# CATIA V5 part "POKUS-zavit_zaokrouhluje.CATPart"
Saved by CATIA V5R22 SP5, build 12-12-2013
Part number: 4980013710
Definition: 4980013710
Nomenclature: 4980013710
Property "GPDM_CREATED_BY": "Peter Cermak"
Property "GPDM_CREATED_ON": "2016-04-12"
Property "GPDM_VERSION": 1
Property "GPDM_MODIFIED_ON": "2016-04-12"
Property "GPDM_MODIFIED_BY": "Peter Cermak"
Property "MATERIAL": "Start_Material"
Property "SURFACE_AREA": 200817
Property "GMASS": "39,707"
Property "DESIGN_NUMBER": "4980013710"
Property "DESIGN_NAME_1": "Engine Housing"
Property "MATURITY": "1"
Property "PLANT": "Please select a location"
Property "DEPARTMENT": "Please select a department"
Property "C3PNG_ItemName": "Engine Housing"
Material "Start_Material": density 100000 kg/m3
Bounding box of the stored display mesh (mm): x 0 to 229.3, y -69 to 197, z -129.7 to 184.7
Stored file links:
  C:\Users\jmaur\Desktop\POKUS-zavit_zaokrouhluje.CATPart
  C:\PWB_XMAP\CATIA_GFT\Material\GFT-CAD-Materials.CATMaterial
  CATMaterial1.CATMaterial
  L:\Antriebe\Projekte\2016\M-16-0005_GET_Gehaeusekonstruktion_8DCL900\8_CAD-Data\int\2016_05_09_FERR_Engine_Housing\4980013710\4980013790.CATPart
  C:\Users\zmuchna\Desktop\Ferrari\motoranschlussgehaeuse\498_housing_fer_cp_cp.CATPart
  L:\Antriebe\Projekte\2016\M-16-0005_GET_Gehaeusekonstruktion_8DCL900\8_CAD-Data\int\2016_05_09_FERR_Engine_Housing\4980013710\4980013710_cp.CATPart
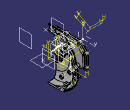
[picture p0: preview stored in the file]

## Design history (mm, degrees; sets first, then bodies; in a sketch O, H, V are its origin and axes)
Parameters
  SURFACE_AREA = 0.200817 (area) {= round(smartWetarea(Body1),"mm2",0)}
  pro_mp_mass = 39.7072 (mass)
  pro_mp_alt_mass = 5 (mass)
  GMASS = 39.7072 (mass)
  pro_mp_source = "Geometry"
AxisSystem1 "M-A-S-T-E-R": origin (0, 0, 0), X (1, 0, 0), Y (0, 1, 0), Z (0, 0, 1)
Set1 "Geometrical Set"
  Line1 "Center_Line": type PtPt, FirstPoint {point type Coord, X -50, Y 0, Z 0}, SecondPoint {point type Coord, X 50, Y 0, Z 0}
  Point1 "Center_Point": (0, 0, 0)
Set2 "Machining_Support"
  Plane1: type Offset, RefPlane Plane6, Offset 1.6
  Plane2 "PL_center_level_1": type Offset, RefPlane Plane5, Offset 12.78, reversed
  Plane3 "PL_center_level_2": type Offset, RefPlane Plane5, Offset 14.78, reversed
Set3
  Plane4 "PL_Flange_Engine_Housing_Front": stored without definition
  Plane5 "PL_Flange_Engine_Housing_Rear": stored without definition
  Plane6 "PL_Oil_Nossel": stored without definition
  Plane7 "PL_Bolts_Contact_Surface_Engine_Side": stored without definition
  Plane8 "PL_Bolts_Contact_Surface_Engine_Side_Lower": stored without definition
  Plane9 "PL_Oil_Nossel_1": stored without definition
  Plane10 "PL_Oil-Riser_2": stored without definition
  Sketch1 "S_Bolts_Differential_Housing_Front", origin (157, 0, 0), H (0, 1, 0), V (0, 0, 1)
    point P1 (65, 142)
    point P2 (150, 138.5)
    point P3 (122.5, -6)
    point P4 (92, -43)
    point P5 (187, 24)
    point P6 (186, 97)
    point P7 (41, -92)
  Sketch2 "S_Bolts_Engine_Housing_Front", origin (209.3, 0, 0), H (0, 1, 0), V (0, 0, 1)
    point P1 (162.619, 38)
    point P2 (107.261, 128)
    point P3 (29, 165)
    point P4 (84, -112.5)
    point P5 (165.5, -16)
  Sketch3 "S_Hydr_Holes", origin (0, 29.4838, 55.6851), H (-1, 0, 0), V (0, -0.8838, 0.4679), geometry linked from another document
  Sketch4 "S_Hydr_Holes_1", origin (0, 43.5217, 82.1981), H (-1, 0, 0), V (0, -0.8838, 0.4679), geometry linked from another document
  Sketch5 "P_Oil_Riser", origin (157.28, 0, 0), H (0, -1, 0), V (0, 0, 1), geometry linked from another document
  Sketch6 "PL_Oil_Riser_2", origin (0, 0, -58), H (1, 0, 0), V (0, -1, 0), geometry linked from another document
Body1 "Rear_Cover" (main body), material "Start_Material"
  Body2 "Raw_Part"
    Solid1: solid without history
  Add1: tool Body2
  Body3 "Machining"
    Body4 "Flanges"
      Body5 "Engine_Flange"
        Sketch7 on Plane4, origin (209.3, 0, 0), H (0, 1, 0), V (0, 0, 1)
          line L1 (-228.2306, 219.2479) -> (234.054, 219.2479)
          line L2 (234.054, 219.2479) -> (234.054, -157.1798)
          line L3 (234.054, -157.1798) -> (-228.2306, -157.1798)
          line L4 (-228.2306, -157.1798) -> (-228.2306, 219.2479)
          horizontal: L1 H, L3 H
          vertical: L2 V, L4 V
          fix: L1, L2, L3, L4
        Pad1: profile Sketch7, direction (1, 0, 0), length 20
      Add2: tool Body5
      Body6 "Diff_Flange"
        Sketch8 on Plane5, origin (157.28, 0, 0), H (0, 1, 0), V (0, 0, -1)
          line L1 (225.392, -220.6587) -> (-229.8439, -220.6587)
          line L2 (-229.8439, -220.6587) -> (-229.8439, 158.3338)
          line L3 (-229.8439, 158.3338) -> (225.392, 158.3338)
          line L4 (225.392, 158.3338) -> (225.392, -220.6587)
          arc A1 centre (0, 0) radius 75 from (70.3464, -26.0075) to (-5.6638, -74.7858) ccw
          intersected line E1 through (29.4838, -55.6851) direction (0.8838, 0.4679) from Plane6
          line L5 (-5.6638, -74.7858) -> (11.4424, -107.0938)
          line L6 (11.4424, -107.0938) -> (90.9813, -64.9801)
          line L7 (90.9813, -64.9801) -> (70.3464, -26.0075)
          radius A1 = 75
          distance L5 O = 40
          distance L5 L7 = 90
          distance L6 O = 100
          horizontal: L1 H, L3 H
          vertical: L2 V, L4 V
          fix: L3, L4, L1, L2
          perpendicularity: L5 E1
          parallelism: L6 E1
        Pad2: profile Sketch8, direction (-1, 0, 0), length 20
      Add3: tool Body6
    Add4: tool Body4
    Body7 "Diff_Flange_Bolts"
      Sketch9 on Plane5, origin (157.28, -70, 142), H (0, 1, 0), V (0, 0, 1)
        point P1 (135, 0)
        reference projected point E1 (135, 0) from Sketch1.P1
        coincidence: P1 E1
      Hole1: placed by Sketch9, at (157.28, 65, 142) direction (1, 0, 0), diameter 9, depth 25, V-bottom angle 130
      UserPattern1: of the body so far, copies 7, at the points of Sketch1
    Add5: tool Body7
    Body8 "Engine_Flange_Bolts"
      Sketch10 on Plane4, origin (209.3, -52, 165), H (0, 1, 0), V (0, 0, 1)
        point P1 (81, 0)
        reference projected point E1 (81, 0) from Sketch2.P3
        coincidence: P1 E1
      Hole2: placed by Sketch10, at (209.3, 29, 165) direction (-1, 0, 0), diameter 9, depth 25, V-bottom angle 130
      UserPattern2: of the body so far, copies 5, at the points of Sketch2
    Add6: tool Body8
    Body9 "Center_machining"
      Sketch11 on ZX plane of AxisSystem1, origin (0, 0, 0), H (1, 0, 0), V (0, 0, 1)
        line L1 (132.1, 32.8) -> (137.5, 32.8)
        line L2 (137.5, 32.8) -> (137.5, 37.8)
        line L3 (137.5, 37.8) -> (142.5, 37.8)
        line L4 (142.5, 37.8) -> (142.5, 32.8)
        point P4 (142.5, 32.8)
        line L5 (142.5, 32.8) -> (148.5, 32.8)
        line L6 (148.5, 32.8) -> (148.5, 39.3)
        line L7 (148.5, 39.3) -> (157.5, 39.3)
        line L8 (157.5, 39.3) -> (157.5, 32.8)
        line L9 (157.5, 32.8) -> (162, 32.8)
        line L10 (162, 32.8) -> (162, 31.25)
        line L11 (162, 31.25) -> (163.5, 31.25)
        line L12 (163.5, 31.25) -> (163.5, 31)
        line L13 (163.5, 31) -> (171.3, 31)
        line L14 (171.3, 31) -> (171.3, 27)
        line L15 (171.3, 27) -> (183.5, 27)
        line L16 (183.5, 27) -> (183.5, 30)
        line L17 (183.5, 30) -> (190, 30)
        line L18 (190, 30) -> (190, 0)
        line L19 (132.1, 32.8) -> (132.1, 40)
        line L20 (132.1, 40) -> (125, 40)
        line L21 (125, 40) -> (125, 0)
        point P19 (125, 0)
        point P20 (190, 0)
        construction line L22 (183.5, 23.9368) -> (182.4657, 23.5603)
        construction arc A1 centre (182.1233, 24.5021) radius 1.0021 from (182.1237, 23.5) to (182.4657, 23.5603) ccw
        construction arc A2 centre (173.4767, 24.5021) radius 1.0021 from (173.1343, 23.5603) to (173.4763, 23.5) ccw
        construction line L23 (173.1343, 23.5603) -> (171.8, 24.046)
        construction arc A3 centre (170.9999, 30.6999) radius 0.3001 from (171.3, 30.7) to (171, 31) ccw
        construction arc A4 centre (161.4998, 32.2998) radius 0.5002 from (162, 32.3) to (161.5, 32.8) ccw
        construction arc A5 centre (156.9998, 38.7998) radius 0.5002 from (157.5, 38.8) to (157, 39.3) ccw
        construction arc A6 centre (149.0002, 38.7998) radius 0.5002 from (149, 39.3) to (148.5, 38.8) ccw
        construction line L24 (133.0856, 32.8) -> (131.7, 33.6)
        distance L9 H = 32.8
        distance L16 V = 183.5
        distance L18 V = 190
        distance L17 H = 30
        distance L1 H = 32.8
        distance L19 V = 132.1
        distance L20 H = 40
        distance L21 V = 125
        distance L7 H = 39.3
        distance L8 V = 157.5
        distance L6 V = 148.5
        distance L4 V = 142.5
        distance L12 V = 163.5
        distance L10 V = 162
        distance L11 H = 31.25
        distance L15 H = 27
        distance L14 V = 171.3
        distance L2 V = 137.5
        distance L3 H = 37.8
        distance L13 H = 31
        horizontal: L1 H, L3 H, L5 H, L7 H, L9 H, L11 H, L13 H, L15 H, L17 H, L20 H
        vertical: L2 V, L4 V, L6 V, L8 V, L10 V, L12 V, L14 V, L16 V, L18 V, L19 V, L21 V
        coincidence: P4 L1, P19 H, P20 H
      Shaft1: profile Sketch11, axis Sketch11.H, angle 360
      Fillet1: radius 0.5, on edge [face of Shaft1 from Sketch11.L7 | face of Shaft1 from Sketch11.L8]; edge [face of Shaft1 from Sketch11.L6 | face of Shaft1 from Sketch11.L7]; edge [face of Shaft1 from Sketch11.L9 | face of Shaft1 from Sketch11.L10]; edge [face of Shaft1 from Sketch11.L3 | face of Shaft1 from Sketch11.L4]
      Fillet2: radius 2.5, on edge [face of Shaft1 from Sketch11.L2 | face of Shaft1 from Sketch11.L3]
      Fillet3: radius 0.2, on edge [face of Shaft1 from Sketch11.L13 | face of Shaft1 from Sketch11.L14]
      Chamfer1: length 1.4, angle 30, on edge [face of Shaft1 from Sketch11.L19 | face of Shaft1 from Sketch11.L1]
      Chamfer2: length 0.5, angle 45, on edge [face of Shaft1 from Sketch11.L14 | face of Shaft1 from Sketch11.L15]
    Add7: tool Body9
    Body10 "Mounting_Contact_Surfaces_Engine_Side"
      Body11 "Mounting_Contact_Surfaces_Engine_Side_Higher"
        Sketch12 on Plane7, origin (187.4, 29, 165), H (0, 1, 0), V (0, 0, -1)
          circle A1 centre (0, 0) radius 12.5
          radius A1 = 12.5
        Pad3: profile Sketch12, direction (-1, 0, 0), length 15
        UserPattern3: of the body so far, copies 5, at the points of Sketch2
      Add8: tool Body11
      Body12 "Mounting_Contact_Surfaces_Engine_Side_Lower"
        Sketch13 on end face of Pad1, origin (229.3, 162.619, 38), H (0, 1, 0), V (0, 0, -1)
          circle A1 centre (0, 0) radius 12.5
          point P1 (0, 0)
          radius A1 = 12.5
          coincidence: P1 O
        Pad4: profile Sketch13, direction (-1, 0, 0), length 15
        UserPattern4: of the body so far, copies 5, at the points of Sketch2
      Add9: tool Body12
    Add10: tool Body10
    Body13 "Oil_Nossel_1_Machining"
      Body14 "Channels_Contact_Surface"
        Sketch14 on Plane9, origin (148, 27.6139, 90.6208), H (-1, 0, 0), V (0, -0.8838, 0.4679)
          line L1 (18, 20) -> (-12, 20)
          line L2 (-12, 20) -> (-12, -60)
          line L3 (-12, -60) -> (18, -60)
          line L4 (18, -60) -> (18, 20)
          distance L1 L3 = 80
          distance V L2 = 12
          length L3 = 30
          distance H L1 = 20
          horizontal: L1 H, L3 H
          vertical: L2 V, L4 V
        Pad5: profile Sketch14, direction (0, 0.4679, 0.8838), length 15
      Add11: tool Body14
    Add12: tool Body13
    Body15 "Oil_Nossel_1_Holes"
      Sketch15 on Plane9, origin (148, 27.6139, 90.6208), H (1, 0, 0), V (0, 0.8838, -0.4679)
        point P1 (0, 0)
        reference projected point E1 (0, 0) from vertex of Sketch4
        coincidence: E1 P1
      Hole3: placed by Sketch15, at (148, 27.6139, 90.6208) direction (0, -0.4679, -0.8838), diameter 6, depth 20, V-bottom angle 130, countersink depth 0.5, countersink angle 90, threaded "M8", thread diameter 8, thread depth 10, pitch 1
      Sketch16 on Plane9, origin (151, 67.3833, 69.564), H (1, 0, 0), V (0, 0.8838, -0.4679)
        point P1 (0, 0)
        reference projected point E1 (0, 0) from vertex of Sketch4
        coincidence: E1 P1
      Hole4: placed by Sketch16, at (151, 67.3833, 69.564) direction (0, -0.4679, -0.8838), diameter 12, depth 68, V-bottom angle 130
      Sketch17 on Plane9, origin (148.5, 67.3833, 69.564), H (1, 0, 0), V (0, 0.8838, -0.4679)
        point P1 (0, 0)
        reference projected point E1 (0, 0) from vertex of Sketch4
        coincidence: E1 P1
      Hole5: placed by Sketch17, at (148.5, 67.3833, 69.564) direction (0, -0.4679, -0.8838), diameter 18, depth 21, countersink depth 2.5, countersink angle 40
      Fillet4: radius 3, on edge [face of Hole5 | face of Hole5]
    Add13: tool Body15
    Body16 "Oil_Nossel_Hole"
      Sketch18 on Plane1, origin (147.4, 30.2324, 57.0992), H (1, 0, 0), V (0, 0.8838, -0.4679)
        point P1 (0, 0)
        reference projected point E1 (0, 0) from vertex of Sketch3
        coincidence: E1 P1
      Hole6: placed by Sketch18, at (147.4, 30.2324, 57.0992) direction (0, -0.4679, -0.8838), diameter 15, depth 18.6, type CounterDrilledType, Diameter 15, DiameterThread 16.5, Pas 1, Sketch Sketch18, ThreadDepth 10, Angle 40, Depth 2.5, Diameter 18
      Fillet5: radius 3, on edge [face of Hole6 | face of Hole6]
      Sketch19 on Plane6, origin (147.4, 29.4838, 55.6851), H (1, 0, 0), V (0, 0.8838, -0.4679)
        point P1 (0, 0)
        reference projected point E1 (0, 0) from vertex of Sketch3
        coincidence: E1 P1
      Hole7: placed by Sketch19, at (147.4, 29.4838, 55.6851) direction (0, -0.4679, -0.8838), diameter 14.5, depth 20.5
    Add14: tool Body16
    Body17 "Center_Machining_Remove_Level_1"
      Sketch20 on Plane2, origin (144.5, 0, 0), H (0, 0, 1), V (0, 1, 0)
        circle A1 centre (21, 6.5) radius 25
        point P1 (21, 6.5)
        radius A1 = 25
        distance H P1 = 6.5
        distance P1 V = 21
      Pad6: profile Sketch20, direction (-1, 0, 0), length 5.3
      Fillet6: radius 0.5, on edge [start face of Pad6 | face of Pad6 from Sketch20.A1]; edge [face of Pad6 from Sketch20.A1 | end face of Pad6]
    Add15: tool Body17
  Remove1: tool Body3
Relations
  rule "Mass_Rule_Part":
    /*Rule created by tfeldbru 05.05.2014*/
    if pro_mp_source == "Geometry"
    	GMASS = pro_mp_mass
    else GMASS =pro_mp_alt_mass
